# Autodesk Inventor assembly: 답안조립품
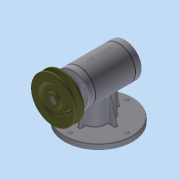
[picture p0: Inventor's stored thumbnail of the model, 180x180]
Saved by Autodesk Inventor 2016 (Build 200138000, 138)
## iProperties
Created: 2018-06
Part Number: 답안조립품
Material: 일반
Document SubType Name: Assembly
Designer: 602-09
Author: 602-09
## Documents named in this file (18)
- C:\Users\602-09\Desktop\380607V1005\답안조립품.iam
- C:\Users\602-09\Desktop\380607V1005\본체.ipt
- C:\Users\602-09\Desktop\380607V1005\V-벨트풀리.ipt
- C:\Users\602-09\Desktop\380607V1005\가변스프링.ipt
- C:\Users\602-09\Desktop\380607V1005\개스킷.ipt
- C:\Users\602-09\Desktop\380607V1005\뒤커버.ipt
- C:\Users\602-09\Desktop\380607V1005\멈춤나사 M3x8.ipt
- C:\Users\602-09\Desktop\380607V1005\베어링 6201.ipt
- C:\Users\602-09\Desktop\380607V1005\베어링 6202.ipt
- C:\Users\602-09\Desktop\380607V1005\본체커버.ipt
- C:\Users\602-09\Desktop\380607V1005\볼트 M3x0.5x8.ipt
- C:\Users\602-09\Desktop\380607V1005\슬라이드.ipt
- C:\Users\602-09\Desktop\380607V1005\앞커버.ipt
- C:\Users\602-09\Desktop\380607V1005\오일 실 12 22 7.ipt
- 오일 실 12 22 7.ipt
- C:\Users\602-09\Desktop\380607V1005\키 4x4x18.ipt
- 키 4x4x18.ipt
- C:\Users\602-09\Desktop\380607V1005\편심축.ipt
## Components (4 placed, 3 different names)
1. V-벨트풀리:1
2. 가변스프링:1
3. 개스킷:1
4. 개스킷:2
